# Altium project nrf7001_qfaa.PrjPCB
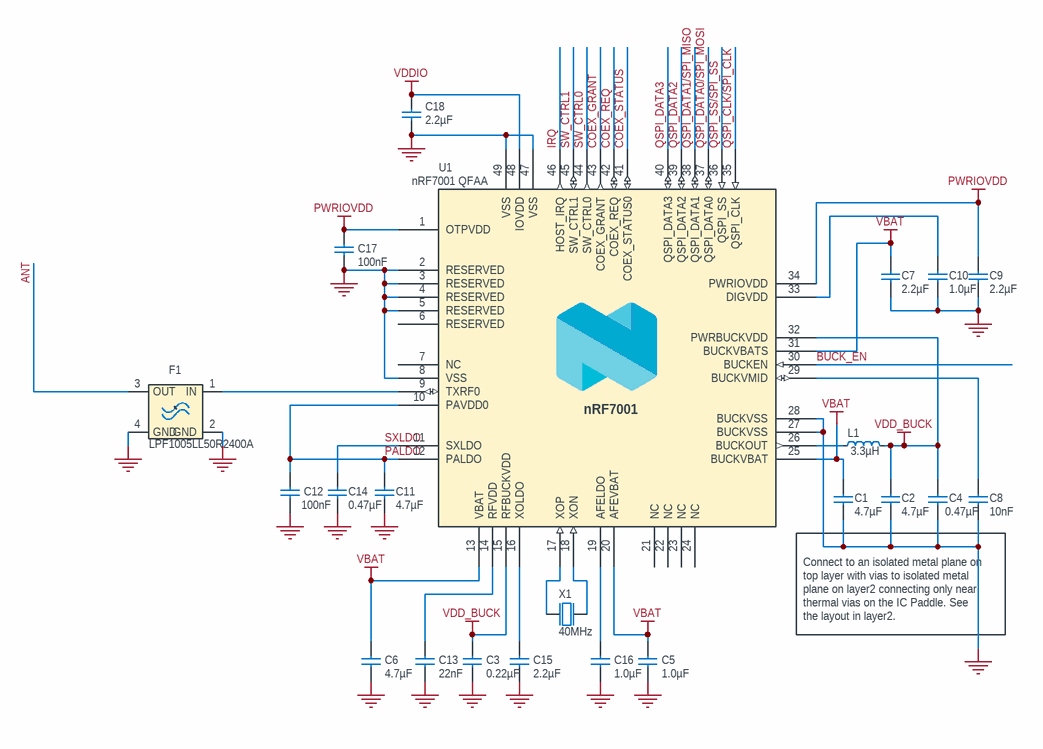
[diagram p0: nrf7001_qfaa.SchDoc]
Revision: 1.1; sheettotal: 1; sheetnumber: 1; RefLayoutTitle: nRF7001 Reference Layout; PCARevision: 1.1; DrawnBy: PRBU; Device: nRF7001; Config: 1; Classification: PUBLIC
1 sheet, 22 parts. Net scope: global (net labels, ports and power ports of the same name join across sheets).
Board file: nrf7001_qfaa.PcbDoc

## Sheet nrf7001_qfaa.SchDoc
size A4; PCAName: nRF7001 Reference Layout; BoardTitle: nRF7001 Reference Layout; Organization: Nordic Semiconductor; Revision: 1.1; SheetNumber: 1; SheetTotal: 1; DrawnBy: PRBU; DocumentSize: A4; RefLayoutTitle: nRF7001 Reference Layout; Device: nRF7001-QFAA

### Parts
C1  4.7µF  [CAPC1608X06L]
C2  4.7µF  [CAPC1608X06L]
C3  0.22µF  [CAPC0603X03L_C]
C4  0.47µF  [CAPC0603X03L_C]
C5  1.0µF  [CAPC1005X04L]
C6  4.7µF  [CAPC1608X06L]
C7  2.2µF  [CAPC1608X06L]
C8  10nF  [CAPC0603X03L_C]
C9  2.2µF  [CAPC1005X04L]
C10  1.0µF  [CAPC1005X04L]
C11  4.7µF  [CAPC1608X06L]
C12  100nF  [CAPC0603X03L_C]
C13  22nF  [CAPC0603X03L_C]
C14  0.47µF  [CAPC0603X03L_C]
C15  2.2µF  [CAPC0603X03L_C]
C16  1.0µF  [CAPC1005X04L]
C17  100nF  [CAPC0603X03L_C]
C18  2.2µF  [CAPC1608X06L]
F1  LPF1005LL50R2400A  [FILTER1005X04L-4pin]
L1  3.3µH  [INDC2520X10N]
U1  nRF7001 QFAA  [QFN40P600X600X60-48N]
X1  40MHz  [BT-XTAL_1612]

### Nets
GND: C1.1 C2.1 C3.1 C4.1 C5.1 C6.1 C7.1 C8.2 C9.1 C10.2 C11.1 C12.1 C13.1 C14.1 C15.1 C16.1 C17.1 C18.1 F1.2(GND) F1.4(GND) U1.2(RESERVED) U1.3(RESERVED) U1.4(RESERVED) U1.5(RESERVED) U1.8(VSS) U1.27(BUCKVSS) U1.28(BUCKVSS) U1.47(VSS) U1.49(VSS) X1.2(GND) X1.4(GND)
PWRIOVDD: C9.2 C17.2 U1.1(OTPVDD) U1.34(PWRIOVDD)
VBAT: C1.2 C5.2 C6.2 C7.2 U1.13(VBAT) U1.20(AFEVBAT) U1.25(BUCKVBAT) U1.31(BUCKVBATS)
VDD_BUCK: C2.2 C3.2 C4.2 L1.2 U1.15(RFBUCKVDD) U1.32(PWRBUCKVDD)
VDDIO: C18.2 U1.48(IOVDD)
ANT: F1.3(OUT)
BUCK_EN: U1.30(BUCKEN)
COEX_GRANT: U1.43(COEX_GRANT)
COEX_REQ: U1.42(COEX_REQ)
COEX_STATUS: U1.41(COEX_STATUS0)
IRQ: U1.46(HOST_IRQ)
PALDO: C11.2 C12.2 U1.10(PAVDD0) U1.12(PALDO)
QSPI_CLK/SPI_CLK: U1.35(QSPI_CLK)
QSPI_DATA0/SPI_MOSI: U1.37(QSPI_DATA0)
QSPI_DATA1/SPI_MISO: U1.38(QSPI_DATA1)
QSPI_DATA2: U1.39(QSPI_DATA2)
QSPI_DATA3: U1.40(QSPI_DATA3)
QSPI_SS/SPI_SS: U1.36(QSPI_SS)
SW_CTRL0: U1.44(SW_CTRL0)
SW_CTRL1: U1.45(SW_CTRL1)
SXLDO: C14.2 U1.11(SXLDO)
NetC8_1: C8.1 U1.29(BUCKVMID)
NetC10_1: C10.1 U1.33(DIGVDD)
NetC13_2: C13.2 U1.14(RFVDD)
NetC15_2: C15.2 U1.16(XOLDO)
NetC16_2: C16.2 U1.19(AFELDO)
NetF1_1: F1.1(IN) U1.9(TXRF0)
NetL1_1: L1.1 U1.26(BUCKOUT)
NetU1_17: U1.17(XOP) X1.3(out)
NetU1_18: U1.18(XON) X1.1(inp)

Not connected (* = marked no-connect by the designer): U1 6(RESERVED) 7(NC) 21(NC) 22(NC) 23(NC) 24(NC)

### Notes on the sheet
- Connect to an isolated metal plane on top layer with vias to isolated metal plane on layer2 connecting only near thermal vias on the IC Paddle. See the layout in layer2.

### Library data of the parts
C1 C2 C6 C11 = C0603-4µ7-25V-X6S-GRM188C81E475KE11: Capacitor, Ceramic, X6S 0603,±10%, 25V; Manufacturer: Murata; Manufacturer Part Number: GRM188C81E475KE11D; Pad Count: 2; Component Status: Active
C3 = C0201-220n-10V-X5R-GRM033R61A224KE90: Capacitor, Ceramic, X5R 0201, ±10%, 10V; Manufacturer: Murata; Manufacturer Part Number: GRM033R61A224KE90D; Pad Count: 2; Component Status: Active
C4 C14 = C0201-470n-6.3V-X5R-GRM033R60J474KE90: Capacitor, Ceramic, X5R 0201,±10%, 6.3V; Manufacturer: Murata; Manufacturer Part Number: GRM033R60J474KE90D; Pad Count: 2; Component Status: Active
C5 = C0402-1µ0-35V-X5R-GRM155R6YA105KE11: Capacitor, Ceramic, X5R 0402,±10%, 35V; Manufacturer: Murata; Manufacturer Part Number: GRM155R6YA105KE11D; Pad Count: 2; Component Status: Active
C7 C18 = C0603-2µ2-16V-X7S-GRM188C71C225KE11: Capacitor, Ceramic, X7S 0603,±10%, 16V; Manufacturer: Murata; Manufacturer Part Number: GRM188C71C225KE11D; Pad Count: 2; Component Status: Active
C8 = C0201-10n-16V-X7R-GRM033R71C103KE14: Capacitor, Ceramic, X7R 0201,±10%, 16V; Manufacturer: Murata; Manufacturer Part Number: GRM033R71C103KE14D; Pad Count: 2; Component Status: Active
C9 = C0402-2µ2-25V-X5R-GRM155R61E225KE11: Capacitor, Ceramic, X5R 0402,±10%, 25V; Manufacturer: Murata; Manufacturer Part Number: GRM155R61E225KE11D; Pad Count: 2; Component Status: Active
C10 = C0402-1µ0-16V-X6S-GRM155C81C105KE11D: Capacitor, Ceramic, X6S 0402,±10%, 16V; Manufacturer: Murata; Pad Count: 2; Component Status: Active
C12 C17 = C0201-100n-16V-X7S-GRM033C71C104KE14: Capacitor, Ceramic, X7S 0201,±10%, 16V; Manufacturer: Murata; Manufacturer Part Number: GRM033C71C104KE14D; Pad Count: 2; Component Status: Active
C13 = C0201-22n-10V-X5R-GRM033R61A223KE84: Capacitor, Ceramic, X5R 0201,±10%, 10V; Manufacturer: Murata; Manufacturer Part Number: GRM033R61A223KE84D; Pad Count: 2; Component Status: Active
C15 = C0201-2µ2-10V-X5R-GRM033R61A225KE47: Capacitor, Ceramic, X5R 0201,±10%, 10V; Manufacturer: Murata; Manufacturer Part Number: GRM033R61A225KE47D; Pad Count: 2; Component Status: Active
C16 = C0402-1µ0-10V-X7S-GRM155C71A105KE11: Capacitor, Ceramic, X7S 0402,±10%, 10V; Manufacturer: Murata; Manufacturer Part Number: GRM155C71A105KE11D; Pad Count: 2; Component Status: Active
F1 = LPF1005LL50R2400A: 2.45GHz Center Frequency Low Pass RF Filter, 100MHz Bandwidth 0.5dB; Manufacturer: Pulse-Electronics-Corporation; Pad Count: 4; Component Status: Active
L1 = L1008-3µ3-LQM2HPN3R3MGCL: Inductor, 1A, ±20%, 200mOhm; Manufacturer: Murata; Pad Count: 2; Component Status: Active
U1 = nRF7001: Wi-Fi Single Band Companion chip; Manufacturer: Nordic Semiconductor; Pad Count: 49; Value: nRF7001-QFAA; Component Status: Active
X1 = XTAL_SMD1612_40MHz_8p_40_85: XTAL SMD 1612, 40MHz, Cl=8pF, Total Tol: ±10ppm, -40-85C; Manufacturer: Abracon Corporation; Manufacturer Part Number: ABM12W-40.0000MHZ-8-D1X-T3; Pad Count: 4; Component Status: Active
